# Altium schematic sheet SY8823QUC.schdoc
size 127 x 101 mm
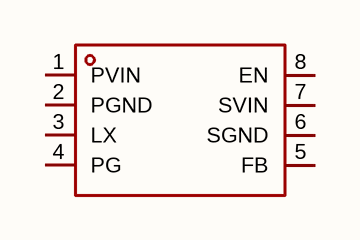
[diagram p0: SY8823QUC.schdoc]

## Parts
U?  sy8823quc  [QFN-8_L2.0-W1.5-P0.45-BL_SILERGY_SY8823QUC]  (value not drawn)

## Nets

Not connected (* = marked no-connect by the designer): U? 1(PVIN) 2(PGND) 3(LX) 4(PG) 5(FB) 6(SGND) 7(SVIN) 8(EN)

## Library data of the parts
U? = sy8823quc: 功能类型:降压型;工作电压:2.5V~5.5V;输出电压:-;输出电流:3.5A;输出类型:可调;; Manufacturer: Silergy(矽力杰); AddInBom: yes; ModelId: 6f1c141e4d904e6c9d6411ca33f8601a; ModelTransform: 75.59,55.9054,0,0,0,0,-1.968,0,0; Function: 降压型; Output Current: 3.5A; Frequency - Switching: 2MHz; Synchronous Rectifier: 是; Number of Outputs: 1; Topology: 降压式; Quiescent Current: 18uA; Switch tube (built-in/external): 内置; Output Type: 可调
